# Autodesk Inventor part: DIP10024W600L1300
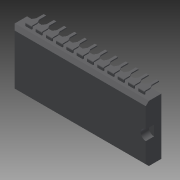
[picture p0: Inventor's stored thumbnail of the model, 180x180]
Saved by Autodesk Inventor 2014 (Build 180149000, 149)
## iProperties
Shininess: 64.0
Length Units: 11272
Angle Units: 11279
Time Units: 11290
Mass Units: 11286
Length Display Precision: 3
Angle Display Precision: 2
Compacted: True
Part Number: DIP10024W600L1300
Document SubType Name: Modeling
Created: 2003-04
Designer: t_enrig
Manufacturer: Standard
Standards Organization: Custom
Density: 1 g/cm^3
Mass: 1.77038 g
Surface Area: 15.4313 cm^2
Volume: 1.77038 cm^3
Material: Generic
Appearance: TranslatedColorStyle
Density: 0.0
Volumn: 0.0
Area: 0.0
PropertySet Name: Model Information
Control State: 0
Master: False
Checked Out: False
Author: t_enrig
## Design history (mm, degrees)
feature "Base1"
body "Solid1"
